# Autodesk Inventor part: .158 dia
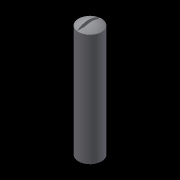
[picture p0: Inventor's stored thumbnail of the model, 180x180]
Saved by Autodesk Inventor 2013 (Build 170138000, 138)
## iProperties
Created: 2013-01
Part Number: .158 dia
Material: Generic
Document SubType Name: Modeling
Designer: John
Density: 1 g/cm^3
Author: John
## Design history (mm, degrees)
sketch "Sketch1"
  geometry: L1 (0, 0)-(0, 19.355); L2 (4.013, 0)-(4.013, 19.355) reference; L3 (2.007, -0.714)-(2.007, 20.069); A1 r 3.175 centre (2.007, 16.894) between (4.013, 19.355) and (2.007, 20.069); A2 r 3.175 centre (2.007, 2.461) between (2.007, -0.714) and (4.013, 0)
  constraints: 6 end point, 4 point on circle, 2 centre point, 2 vertical
  dimensions: "d2" = 3.175 radius of A1; "d3" = 3.175 radius of A2
revolve "Revolution1" sketch "Sketch1" stored, may be unused: angle "d4" = 90 deg
sketch "Sketch2"
  geometry: L1 (0, 0)-(4.013, 0) reference; L2 (2.261, 19.355)-(2.261, 20.059); L3 (2.261, 19.355)-(1.753, 19.355); L4 (1.753, 19.355)-(1.753, 20.059); L5 (1.753, 0)-(1.753, -0.704); L6 (2.261, 0)-(1.753, 0); L7 (2.261, 0)-(2.261, -0.704); A1 r 3.175 centre (2.007, 16.894) between (4.013, 19.355) and (0, 19.355) reference; A2 r 3.175 centre (2.007, 2.461) between (0, 0) and (4.013, 0) reference
  constraints: 12 end point, 4 point on circle, 2 perpendicular
  dimensions: "d6" = 0.508 distance of L2.start L3.end
extrude "Extrusion1" cut sketch "Sketch2" stored distance "d7" = 25.4; taper "d8" = 0 deg
body "Solid1"
